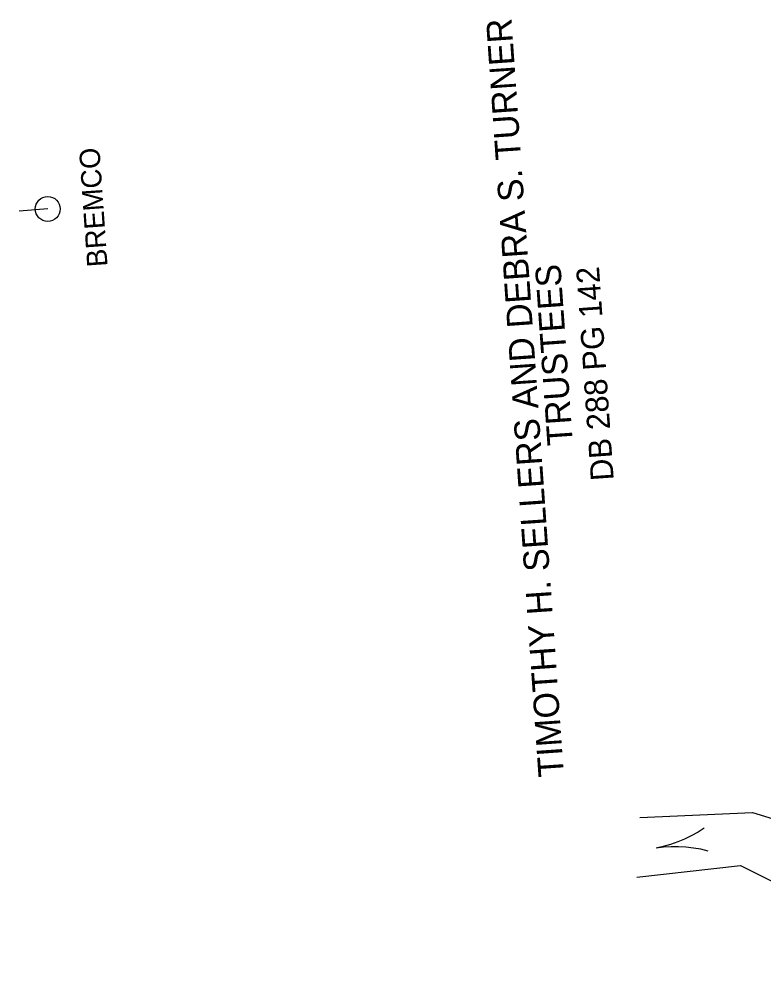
# Model space of a CAD drawing. Extents: x 1365957 to 1366704, y 992284 to 993271.
# Drawn here: x 1365971.9 to 1366118.1, y 992903 to 993091.7 of the extents above; entities that cross this region are included whole.
import ezdxf

# ---------------------------------------------------------------- set-up
doc = ezdxf.new("R2010")
doc.units = 0
for name, color, linetype in [('Exist Hydro Stream Flow Arrow CELL', 7, 'Continuous'), ('Exist Hydro Stream or Body of Water', 7, 'Continuous'), ('Exist Property Deed Book Text', 7, 'Continuous'), ('Exist Property Owner Text', 7, 'Continuous'), ('Exist Utilities Power Joint Use Telephone Text', 7, 'Continuous'), ('Exist Utilities Power Pole CELL', 7, 'Continuous')]:
    doc.layers.add(name, color=color, linetype=linetype)

msp = doc.modelspace()

# ---------------------------------------------------------------- linework, layer by layer
at = {"layer": 'Exist Hydro Stream Flow Arrow CELL'}
msp.add_line((1366101.89, 992929.68), (1366101.89, 992929.68), dxfattribs=at)
for points in [[(1366106.44, 992932.77), (1366105.22, 992931.95), (1366103.89, 992931.26), (1366102.57, 992930.6), (1366101.23, 992930.05), (1366099.83, 992929.58), (1366098.39, 992929.17), (1366096.96, 992928.85)], [(1366107.2, 992928.25), (1366105.78, 992928.62), (1366104.3, 992928.84), (1366102.83, 992929.04), (1366101.39, 992929.12), (1366099.91, 992929.11), (1366098.41, 992929.02), (1366096.96, 992928.85)]]:
    msp.add_lwpolyline(points, dxfattribs=at)
at = {"layer": 'Exist Hydro Stream or Body of Water'}
for points in [[(1366093.76, 992934.89), (1366115.88, 992935.85), (1366135.11, 992929.97)], [(1366093.19, 992923.14), (1366113.57, 992925.45), (1366137.77, 992913.36), (1366201.95, 992893.6), (1366232.22, 992890.91), (1366257.57, 992885.07), (1366276.96, 992869.22), (1366301.86, 992863.77), (1366317.67, 992855.76), (1366332.55, 992843.55)]]:
    msp.add_lwpolyline(points, dxfattribs=at)
at = {"layer": 'Exist Utilities Power Pole CELL'}
for q in [(1365971.85, 993053.99), (1365977.46, 993054.39)]:
    msp.add_line((1365977.46, 993054.39), q, dxfattribs=at)
msp.add_circle((1365977.46, 993054.39), 2.45, dxfattribs=at)

# ---------------------------------------------------------------- texts
at = {"layer": 'Exist Property Deed Book Text'}
msp.add_text('DB 288 PG 142', height=4.5, rotation=93.9691, dxfattribs=at).set_placement((1366088.66, 993001.16))
at = {"layer": 'Exist Property Owner Text'}
for s, p in [('TIMOTHY H. SELLERS AND DEBRA S. TURNER', (1366078.87, 992942.99)), ('TRUSTEES', (1366080.63, 993008.11))]:
    msp.add_text(s, height=5, rotation=93.9691, dxfattribs=at).set_placement(p)
at = {"layer": 'Exist Utilities Power Joint Use Telephone Text'}
msp.add_text('BREMCO', height=4, rotation=93.9691, dxfattribs=at).set_placement((1365989.22, 993043.13))

doc.saveas('drawing.dxf')
